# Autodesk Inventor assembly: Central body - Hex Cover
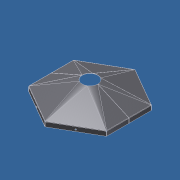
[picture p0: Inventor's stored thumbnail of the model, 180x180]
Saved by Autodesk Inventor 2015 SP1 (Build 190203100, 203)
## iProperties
Category: Mechanical Engineering Drawing and Design - CADD
Manager: Fábio Ricardo de Oliveira Souza
Company: SENAI - Serviço Nacional de Aprendizagem Industrial
Created: 2011-06
Part Number: Central body - Hex Cover
Document SubType Name: Weldment
Designer: Guilherme Augusto Franco de Souza
Engineer: George Geraldo de Oliveia Silva
Authority: Fábio Ricardo de Oliveira Soza
Weld Material: Welded Stainless Steel, 440C
Description: Stainless Steel (DIN- X6NiCrTi18-10)
Subject: WorldSkill 2011 - London, England
Author: Guilherme Augusto Franco de Souza
Revision Number: 00
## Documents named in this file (2)
- E:\Visitor Experience Project\WSI2015 - Visitor Experience Project\#46- Sheet Metal Technology\01- 3D Models\Outodoor Heater\2- Assemblies\Central body - Hex Cover.iam
- E:\Visitor Experience Project\WSI2015 - Visitor Experience Project\#46- Sheet Metal Technology\01- 3D Models\Outodoor Heater\1- Parts\Cantral body - Hex cover.ipt
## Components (2 placed, 1 different names)
1. Cantral body - Hex cover:1
2. Cantral body - Hex cover:2
